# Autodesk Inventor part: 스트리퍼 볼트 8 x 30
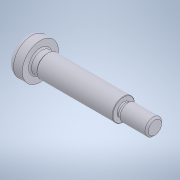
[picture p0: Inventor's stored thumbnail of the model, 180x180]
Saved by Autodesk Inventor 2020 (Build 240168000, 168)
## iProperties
Created: 2024-04
Part Number: 스트리퍼 볼트 8 x 30
Material: 강철, 연강
Description: 6각 소켓 머리 숄더 나사
Document SubType Name: Modeling
Designer: oem
Density: 7.86 g/cm^3
Appearance: 기본값
Author: jhkim
Sending System: Autodesk Inventor 2025
Preprocessor: ST-DEVELOPER v20
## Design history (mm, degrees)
feature "Solid1"
node "솔리드1"
